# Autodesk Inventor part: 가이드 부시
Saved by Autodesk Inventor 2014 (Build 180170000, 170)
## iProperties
Created: 2026-09
Part Number: 가이드 부시
Material: 일반
Document SubType Name: Modeling
Designer: dg
Density: 1 g/cm^3
Appearance: 기본값
Author: dg
Author: jhkim
Creation Date: 2026-08-27
Sending System: Autodesk Inventor 2027
Preprocessor: ST-DEVELOPER v20.1
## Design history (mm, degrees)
node "가이드 부시1"
node "솔리드1"
node "기준1"
